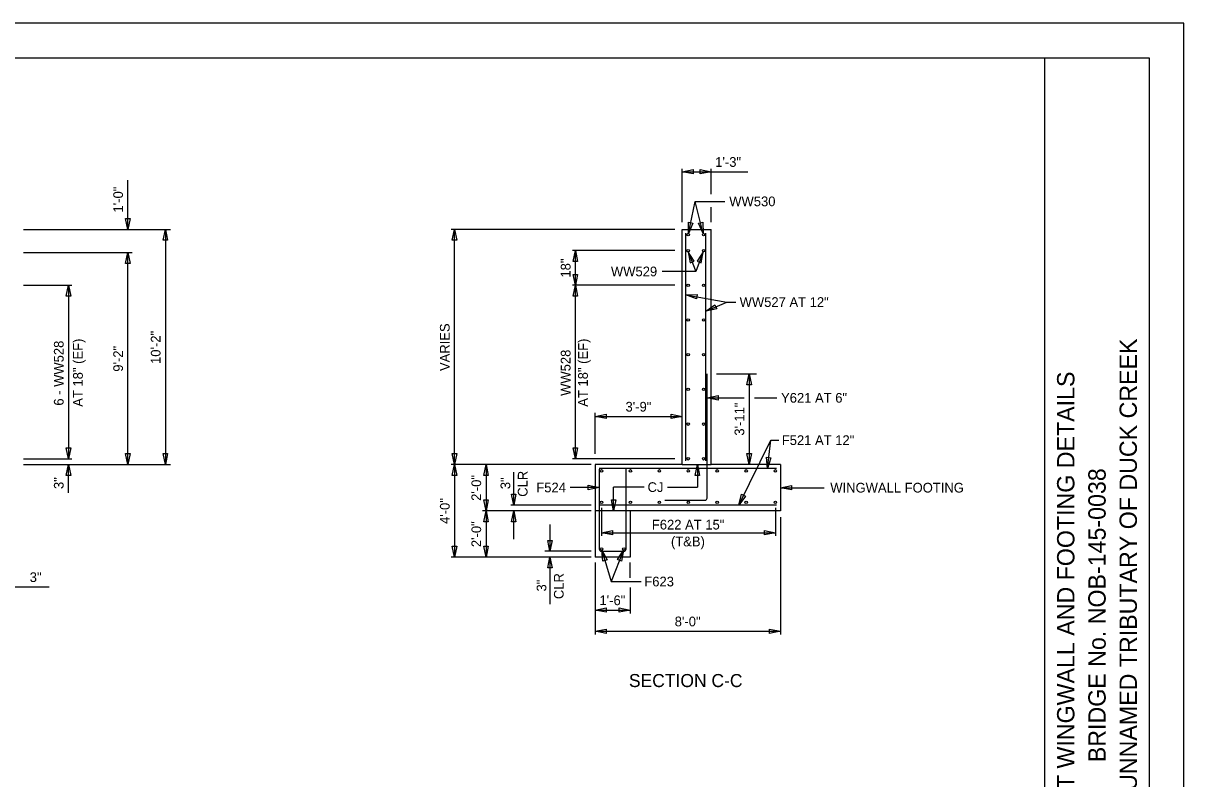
# Model space of a CAD drawing. Extents: x -375 to 456, y -77 to 177.
# Drawn here: x 51.9 to 102, y -43.6 to -11 of the extents above; entities that cross this region are included whole.
import ezdxf

# ---------------------------------------------------------------- set-up
doc = ezdxf.new("R2010")
doc.units = 0
for name, color, linetype in [('BR_P_Gen_Text', 7, 'Continuous'), ('BR_P_Slab_Reinforcing', 7, 'Continuous'), ('BR_P_Sub_Deep_Reinforcing', 7, 'Continuous'), ('DR_P_Culvert', 7, 'Continuous'), ('SH_Border', 7, 'Continuous'), ('SH_Cut_Line', 7, 'Continuous'), ('SH_Data', 7, 'Continuous'), ('TX_P_1', 7, 'Continuous')]:
    doc.layers.add(name, color=color, linetype=linetype)

msp = doc.modelspace()

# ---------------------------------------------------------------- linework, layer by layer
at = {"layer": 'BR_P_Gen_Text'}
for points in [[(80.797, -17.3), (80.797, -17.489), (80.325, -17.394)], [(81.102, -17.489), (81.102, -17.3), (81.575, -17.394)], [(56.283, -19.416), (56.472, -19.416), (56.378, -19.889)], [(58.096, -20.361), (57.907, -20.361), (58.001, -19.889)], [(70.586, -20.361), (70.397, -20.361), (70.492, -19.889)], [(80.606, -19.577), (80.791, -19.616), (80.6, -20.059)], [(81.034, -19.624), (81.218, -19.578), (81.241, -20.059)], [(56.472, -21.361), (56.283, -21.361), (56.378, -20.889)], [(75.808, -21.278), (75.619, -21.278), (75.714, -20.806)], [(80.671, -21.335), (80.848, -21.267), (80.591, -20.86)], [(80.977, -21.268), (81.154, -21.335), (81.232, -20.859)], [(75.619, -21.833), (75.808, -21.833), (75.714, -22.306)], [(53.909, -22.778), (53.72, -22.778), (53.814, -22.306)], [(75.808, -22.778), (75.619, -22.778), (75.714, -22.306)], [(80.973, -22.705), (80.94, -22.892), (80.492, -22.715)], [(81.745, -23.148), (81.819, -23.322), (81.348, -23.422)], [(83.317, -26.608), (83.128, -26.608), (83.222, -26.136)], [(81.881, -27.077), (81.881, -27.266), (81.408, -27.171)], [(77.047, -27.881), (77.047, -28.07), (76.575, -27.976)], [(79.852, -28.07), (79.852, -27.881), (80.325, -27.976)], [(53.72, -29.333), (53.909, -29.333), (53.814, -29.806)], [(56.283, -29.583), (56.472, -29.583), (56.378, -30.056)], [(57.907, -29.583), (58.096, -29.583), (58.001, -30.056)], [(70.397, -29.583), (70.586, -29.583), (70.492, -30.056)], [(75.619, -29.333), (75.808, -29.333), (75.714, -29.806)], [(83.128, -29.583), (83.317, -29.583), (83.222, -30.056)], [(53.909, -30.528), (53.72, -30.528), (53.814, -30.056)], [(70.586, -30.528), (70.397, -30.528), (70.492, -30.056)], [(71.947, -30.528), (71.758, -30.528), (71.853, -30.056)], [(81.082, -30.528), (80.893, -30.528), (80.988, -30.056)], [(83.975, -29.742), (84.163, -29.765), (84.011, -30.222)], [(76.269, -31.142), (76.269, -30.953), (76.742, -31.048)], [(85.047, -30.961), (85.047, -31.15), (84.575, -31.056)], [(71.758, -31.583), (71.947, -31.583), (71.853, -32.056)], [(72.957, -31.333), (73.146, -31.333), (73.051, -31.806)], [(77.27, -31.583), (77.459, -31.583), (77.365, -32.056)], [(82.898, -31.34), (83.067, -31.424), (82.773, -31.806)], [(71.947, -32.528), (71.758, -32.528), (71.853, -32.056)], [(73.146, -32.528), (72.957, -32.528), (73.051, -32.056)], [(77.314, -32.911), (77.314, -33.1), (76.842, -33.006)], [(83.882, -33.1), (83.882, -32.911), (84.355, -33.006)], [(70.397, -33.583), (70.586, -33.583), (70.492, -34.056)], [(71.758, -33.583), (71.947, -33.583), (71.853, -34.056)], [(74.517, -33.333), (74.706, -33.333), (74.612, -33.806)], [(74.706, -34.528), (74.517, -34.528), (74.612, -34.056)], [(77.084, -34.182), (76.903, -34.237), (76.857, -33.757)], [(77.707, -34.231), (77.531, -34.163), (77.789, -33.756)], [(77.047, -36.251), (77.047, -36.44), (76.575, -36.345)], [(77.602, -36.44), (77.602, -36.251), (78.075, -36.345)], [(77.047, -37.166), (77.047, -37.355), (76.575, -37.26)], [(84.102, -37.355), (84.102, -37.166), (84.575, -37.26)]]:
    msp.add_lwpolyline(points, close=True, dxfattribs=at)
at = {"layer": 'BR_P_Slab_Reinforcing'}
for centre in [(80.588, -20.112), (81.254, -20.112), (80.588, -20.806), (81.254, -20.806), (80.588, -22.306), (81.254, -22.306), (80.588, -23.806), (81.254, -23.806), (80.588, -25.306), (81.254, -25.306), (80.588, -26.806), (81.254, -26.806), (80.588, -28.306), (81.254, -28.306), (80.588, -29.806), (81.254, -29.806), (76.842, -30.33), (78.092, -30.33), (79.342, -30.33), (80.592, -30.33), (81.842, -30.33), (83.092, -30.33), (84.355, -30.33), (76.842, -31.692), (78.092, -31.692), (79.342, -31.692), (80.592, -31.692), (81.842, -31.692), (83.092, -31.692), (84.355, -31.692), (76.842, -33.706), (77.808, -33.706)]:
    msp.add_circle(centre, 0.0542, dxfattribs=at)
at = {"layer": 'BR_P_Sub_Deep_Reinforcing'}
for p, q in [((80.492, -29.889), (80.492, -20.056)), ((81.348, -29.889), (81.348, -20.056)), ((81.408, -31.502), (81.408, -26.136)), ((84.408, -30.222), (76.742, -30.222)), ((76.742, -30.26), (76.742, -33.706)), ((77.908, -33.706), (77.908, -30.26)), ((84.408, -31.806), (76.742, -31.806)), ((79.578, -31.602), (81.308, -31.602)), ((76.842, -33.806), (77.808, -33.806))]:
    msp.add_line(p, q, dxfattribs=at)
for centre, start, end in [((81.308, -31.502), 270, 360), ((76.842, -33.706), 180, 270), ((77.808, -33.706), 270, 360)]:
    msp.add_arc(centre, 0.1, start, end, dxfattribs=at)
at = {"layer": 'DR_P_Culvert'}
for p, q in [((80.325, -30.056), (80.325, -19.889)), ((80.325, -19.889), (81.575, -19.889)), ((81.575, -30.056), (81.575, -19.889)), ((80.325, -30.056), (76.575, -30.056)), ((76.575, -30.056), (76.575, -34.056)), ((80.325, -30.056), (81.575, -30.056)), ((84.575, -30.056), (81.575, -30.056)), ((84.575, -30.056), (84.575, -32.056)), ((78.075, -32.056), (76.575, -32.056)), ((84.575, -32.056), (78.075, -32.056)), ((78.075, -32.056), (78.075, -34.056)), ((78.075, -34.056), (76.575, -34.056))]:
    msp.add_line(p, q, dxfattribs=at)
at = {"layer": 'SH_Border'}
msp.add_line((96, -75.474), (96, -12.474), dxfattribs=at)
msp.add_lwpolyline([(4.5, -12.474), (100.5, -12.474), (100.5, -75.474), (4.5, -75.474)], close=True, dxfattribs=at)
at = {"layer": 'SH_Cut_Line'}
msp.add_lwpolyline([(0, -76.974), (102, -76.974), (102, -10.974), (0, -10.974)], close=True, dxfattribs=at)
at = {"layer": 'TX_P_1'}
for p, q in [((80.325, -19.574), (80.325, -17.264)), ((80.325, -17.394), (83.164, -17.394)), ((81.575, -18.368), (81.575, -17.264)), ((56.378, -19.889), (56.378, -17.757)), ((80.6, -20.059), (80.895, -18.677)), ((81.241, -20.059), (80.895, -18.677)), ((80.895, -18.677), (82.168, -18.677)), ((81.575, -19.574), (81.575, -18.934)), ((51.869, -19.889), (58.226, -19.889)), ((58.001, -19.889), (58.001, -30.056)), ((80.014, -19.889), (70.351, -19.889)), ((70.492, -30.056), (70.492, -19.889)), ((51.869, -20.889), (56.561, -20.889)), ((56.378, -30.056), (56.378, -20.889)), ((80.014, -20.806), (75.591, -20.806)), ((75.714, -22.306), (75.714, -20.806)), ((80.591, -20.86), (80.914, -21.707)), ((81.232, -20.859), (80.914, -21.707)), ((80.914, -21.707), (79.469, -21.707)), ((51.869, -22.306), (53.965, -22.306)), ((53.814, -22.306), (53.814, -29.806)), ((80.014, -22.306), (75.591, -22.306)), ((75.714, -29.806), (75.714, -22.306)), ((80.492, -22.715), (82.254, -23.031)), ((81.348, -23.422), (82.254, -23.031)), ((82.254, -23.031), (82.645, -23.031)), ((81.811, -26.136), (83.543, -26.136)), ((83.222, -26.136), (83.222, -30.056)), ((81.408, -27.171), (83.011, -27.171)), ((83.459, -27.171), (84.412, -27.171)), ((76.575, -29.592), (76.575, -27.82)), ((76.575, -27.976), (80.325, -27.976)), ((82.773, -31.806), (84.161, -29.001)), ((84.011, -30.222), (84.161, -29.001)), ((84.161, -29.001), (84.51, -29.001)), ((51.869, -29.806), (53.965, -29.806)), ((51.869, -30.056), (58.226, -30.056)), ((53.814, -31.278), (53.814, -30.056)), ((76.391, -30.056), (70.351, -30.056)), ((70.492, -30.056), (70.492, -34.056)), ((71.853, -30.056), (71.853, -32.056)), ((80.014, -29.806), (75.591, -29.806)), ((80.988, -30.056), (80.988, -31.031)), ((73.051, -31.806), (73.051, -30.39)), ((76.742, -31.048), (75.492, -31.048)), ((78.683, -31.031), (77.365, -31.031)), ((77.365, -32.056), (77.365, -31.031)), ((79.688, -31.031), (80.988, -31.031)), ((84.575, -31.056), (86.457, -31.056)), ((76.391, -32.056), (71.703, -32.056)), ((71.853, -32.056), (71.853, -34.056)), ((76.391, -31.806), (72.928, -31.806)), ((73.051, -33.278), (73.051, -32.056)), ((76.842, -31.929), (76.842, -33.137)), ((84.355, -31.929), (84.355, -33.137)), ((84.575, -32.335), (84.575, -37.397)), ((74.612, -32.649), (74.612, -33.806)), ((76.842, -33.006), (84.355, -33.006)), ((76.391, -34.056), (70.351, -34.056)), ((76.391, -33.806), (74.398, -33.806)), ((74.612, -34.056), (74.612, -36.085)), ((76.857, -33.757), (77.267, -35.114)), ((77.789, -33.756), (77.267, -35.114)), ((76.575, -34.296), (76.575, -37.397)), ((78.075, -34.959), (78.075, -34.296)), ((51.373, -35.345), (52.983, -35.345)), ((77.267, -35.114), (78.554, -35.114)), ((78.075, -35.366), (78.075, -36.498)), ((76.575, -36.345), (78.075, -36.345)), ((76.575, -37.26), (84.575, -37.26))]:
    msp.add_line(p, q, dxfattribs=at)

# ---------------------------------------------------------------- texts
at = {"layer": 'SH_Data'}
for s, p in [('OVER UNNAMED TRIBUTARY OF DUCK CREEK', (99.975, -47.286)), ('INLET WINGWALL AND FOOTING DETAILS', (97.275, -46.319)), ('BRIDGE No. NOB-145-0038', (98.625, -42.925))]:
    msp.add_text(s, height=0.75, rotation=90, dxfattribs=at).set_placement(p)
msp.add_text('SECTION C-C', height=0.56461, dxfattribs=at).set_placement((78.027, -39.677))
at = {"layer": 'TX_P_1'}
for s, p in [('1\'-3"', (81.755, -17.184)), ('WW530', (82.362, -18.887)), ('WW529', (77.25, -21.917)), ('WW527 AT 12"', (82.81, -23.241)), ('Y621 AT 6"', (84.6, -27.381)), ('3\'-9"', (77.88, -27.766)), ('F521 AT 12"', (84.631, -29.211)), ('F524', (74.025, -31.258)), ('CJ', (78.833, -31.241)), ('WINGWALL FOOTING', (86.727, -31.266)), ('F622 AT 15"', (79.018, -32.864)), ('(T&B)', (79.843, -33.592)), ('3"', (52.138, -35.135)), ('F623', (78.692, -35.324)), ('1\'-6"', (76.755, -36.135)), ('8\'-0"', (80.005, -37.05))]:
    msp.add_text(s, height=0.42, dxfattribs=at).set_placement(p)
for s, p in [('1\'-0"', (56.168, -19.158)), ('18"', (75.504, -21.972)), ('VARIES', (70.282, -26.012)), ('10\'-2"', (57.791, -25.706)), ('6 - WW528', (53.604, -27.509)), ('AT 18" (EF)', (54.431, -27.557)), ('9\'-2"', (56.168, -26.043)), ('AT 18" (EF)', (76.252, -27.557)), ('WW528', (75.504, -27.086)), ('3\'-11"', (83.012, -28.807)), ('2\'-0"', (71.643, -31.626)), ('CLR', (73.647, -31.45)), ('3"', (53.604, -31.114)), ('3"', (72.901, -31.121)), ('4\'-0"', (70.282, -32.626)), ('2\'-0"', (71.643, -33.626)), ('3"', (74.461, -35.544)), ('CLR', (75.208, -35.873))]:
    msp.add_text(s, height=0.42, rotation=90, dxfattribs=at).set_placement(p)

doc.saveas('drawing.dxf')
